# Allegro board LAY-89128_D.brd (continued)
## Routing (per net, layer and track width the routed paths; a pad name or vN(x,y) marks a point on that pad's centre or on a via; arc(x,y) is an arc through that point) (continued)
P3V3_SDA: length 29.5
  TOP w0.203: C79.1 155.04,44.04 U25.1
  TOP w0.305: v2(163.62,37.16) 164.03,37.57 C155.1 ; v2(150.39,38.02) 150.01,37.64 U27.5 ; C160.1 162.6,42.19 v2(162.9,42.49)
  TOP w0.381: R202.1 163.67,46.29 v2(163.74,46.36) 164.34,46.96 C94.1
  TOP w0.457: v2(171.42,43.71) 171.42,43.48 170.97,43.03 170.57,43.03 C82.1
  TOP w0.508: v2(166.24,35.5) 166.27,35.54 R197.1 ; v2(165.03,47.95) 165.03,47.91 165.47,47.48 165.47,46.93 C83.1 ; R186.1 157.56,45.03 v2(156.79,45.8)
  BOTTOM w0.254: U26.7 169.35,46.04 169.66,46.35 169.87,46.35 169.9,46.38 169.9,46.38 v3(170.26,46.74) ; U26.11 171.2,43.93 v2(171.42,43.71) ; U28.1 164.12,37.45 163.83,37.16 v2(163.62,37.16) ; U19.1 160.57,38.09 v3(160.46,38.2)
  BOTTOM w0.305: U29.1 162.6,42.11 162.9,42.41 v2(162.9,42.49) ; v2(165.03,47.95) 165.03,47.92 165.43,47.53 165.43,46.95 166.35,46.02 U26.1
  BOTTOM w0.381: R199.1 v2(173.41,35.93) ; v3(156.03,47.88) 156.78,47.13 156.78,45.81 v2(156.79,45.8) ; v2(163.74,46.36) 163.8,46.3 U20.1
  BOTTOM w0.508: C80.1 R190.2 ; C80.1 R187.1 ; C80.1 149.5,37.77 149.76,38.02 v2(150.39,38.02)
  vias: v3(159.71,42.07)
P5V0_SDA_USB_CONN_VBUS: length 6.7
  TOP w0.381: J57.1 180.84,40.15 179.66,38.97 L4.1 179.46,38.97 178.58,39.85 177.35,39.85 176.97,40.23 U17.6
P5V_SDA: length 2.7
  TOP w0.508: R198.1 170.05,39.12 v2(170.73,39.79)
  BOTTOM w0.305: v2(169.26,46.96) 169.26,46.62 168.85,46.22 U26.6
  vias: v2(177.1,36.09) v2(177.1,34.82) v2(178.37,36.09) v2(178.37,34.82) v3(165.65,45.69)
VBAT: length 2.2
  TOP w0.508: v2(97.43,37.38) 97.99,37.95 P1.49
  vias: v2(96.54,36.24) v2(96.54,35.1) v2(97.56,36.24) v2(97.56,35.1)
VBATPWR: length 2
  TOP w0.508: P1.46 v2(101.8,41.42)
  vias: v2(100.86,41.7) v2(100.86,40.81)
VBUS_DC: length 5.1
  TOP w0.305: J7.B4 158.24,53.29 157.99,53.04 J7.A9 157.99,51.53 157.68,51.23 ; J7.B9 160.74,53.29 160.99,53.04 J7.A4 160.99,51.81 161.16,51.64
  vias: v2(158.22,49.71)
VBUS_PA: length 6.1
  TOP w0.305: D4.C 176.58,50.98 176.99,51.39 J6.A4 176.99,53.04 176.74,53.29 J6.B9 ; v2(173.99,51.51) J6.A9 173.99,53.04 174.24,53.29 J6.B4
VDDIO: length 2.1
  TOP w0.508: v2(104.34,37.28) v2(104.34,38.17) P1.44
  vias: v2(106.95,40.56) v2(107.97,40.56) v2(109.04,40.64) v2(110.89,41.45)
VDDIO_BRD: length 54.5
  TOP w0.305: Q1.1 123.73,43.43 124.1,43.05 v2(129.23,43.05)
  TOP w0.508: v2(120.06,9.35) 119.63,9.78 R71.2 ; v2(120.06,9.35) 120.39,9.35 120.9,9.86 R56.2 ; v2(120.06,9.35) 120.75,8.67 122.72,8.67 123.44,9.38 R67.2 124.14,10.08 124.38,10.33 v2(124.38,16.76) 124.38,17.01 J28.1 ; J12.2 95.13,8.09 96.35,9.31 R7.2 ; R91.1 R90.1 111.45,30.98 v2(111.66,31.19)
  BOTTOM w0.305: SH7.2 131.01,41.27 v2(129.23,43.05)
  BOTTOM w0.381: R69.1 175.54,15.2 R62.1 175.54,13.41 175.08,12.95 v2(174.07,12.95)
  BOTTOM w0.457: SH6.1 118.44,41.25 v2(118.41,41.27)
  BOTTOM w0.508: TP6.1 123.11,15.49 v2(124.38,16.76) ; v2(120.06,9.35) 119.71,9.7 R68.1 ; SH5.1 114.97,39.3 v2(115.43,39.75)
  vias: v2(171.1,11.47) v2(171.11,10.31) v2(171.22,12.49) v2(172.37,11.47) v2(172.38,10.31) v2(172.49,12.49)
VDDPA: length 2.5
  TOP w0.508: 94.18,39.4 v2(94.18,38.09)
  BOTTOM w0.508: R26.2 v2(94.18,38.09)
ANT_1: length 554.1
  TOP w0.4: J29.2 51.81,28.73 51.52,29.01 47.31,29.01 arc(47.11,28.97) 46.93,28.85 46.73,28.65 arc(46.71,28.62) 46.7,28.58 46.7,7.9 arc(46.59,7.62) 46.3,7.5 2.1,7.5 arc(1.82,7.62) 1.7,7.9 1.7,52.1 arc(1.82,52.38) 2.1,52.5 46.3,52.5 arc(46.58,52.38) 46.7,52.1 46.7,29.75 46.1,29.15 46.1,8.5 arc(45.98,8.22) 45.7,8.1 2.7,8.1 arc(2.42,8.22) 2.3,8.5 2.3,51.5 arc(2.42,51.78) 2.7,51.9 45.7,51.9 arc(45.98,51.78) 46.1,51.5 46.1,30.15 45.5,29.55 45.5,9.1 arc(45.38,8.82) 45.1,8.7 3.3,8.7 arc(3.02,8.82) 2.9,9.1 2.9,50.9 arc(3.02,51.18) 3.3,51.3 45.1,51.3 arc(45.38,51.18) 45.5,50.9 v2(45.5,31)
  TOP w0.505: R80.2 R73.2 59.41,28.72 59.4,28.73 J30.2 J29.2 ; J29.3 J30.3 59.41,31.27 59.42,31.27 R79.2 60.23,31.28 R74.2
  BOTTOM w0.4: v2(45.5,31) 51.74,31 arc(51.93,31.08) J29.3
C_TX1: length 11.5
  TOP w0.505: C105.2 C97.2 ; C97.2 R75.2 ; C97.2 65.64,33.17 C95.2 63.75,33.19 C98.2 62.18,33.16 R74.1 62.16,31.28 R79.1
C_TX2: length 11.5
  TOP w0.505: C103.2 R81.2 ; C103.2 65.64,26.82 C100.1 C96.1 R80.1 R73.1 ; C103.2 C101.2
DC5V: length 18.1
  TOP w0.508: 151.59,23.88 152.88,22.58 154.89,22.58 155.49,21.98 155.49,16.09 v2(152.84,13.45)
  BOTTOM w0.508: C134.1 129.92,33.87 129.55,33.5 J43.4 ; SJ10.1 152.84,12.15 v2(152.84,13.45)
EXT_MODE_SWITCH_SP: length 40.2
  BOTTOM w0.114: J27.6 185.39,27.21 185.39,31.55 184.41,32.53 179.09,32.53 177.83,33.79 177.75,33.79 177.74,33.79 158.44,33.79 155.53,36.7 154.5,36.7 153.87,36.07 R144.2
EXT_MODE_SWITCH_SP_DONE: length 41.4
  BOTTOM w0.114: R122.1 155.27,36.07 157.8,33.54 177.73,33.54 178.99,32.29 184.31,32.29 185.15,31.45 185.15,28.06 184.05,26.97 183.7,26.97 183.1,26.37 183.1,24.43 J27.8
EXTAL32: length 2.8
  TOP w0.114: Y1.1 119.3,38.5 120.36,37.43 120.36,36.8 U22.L5
GREEN_LED: length 25.6
  TOP w0.114: v1(158.34,12.12) 157.28,12.12 155.92,13.47 155.92,23.73 156.15,23.96 R15.2 156.51,24.85 156.43,24.94 154.74,24.94 J43.19
  BOTTOM w0.114: v1(158.34,12.12) 158.76,12.12 158.79,12.15 SJ8.1
J_VBATPWR:
  vias: v2(106.27,44.91) v2(106.27,43.89) v2(106.27,42.88)
J_VUP:
  vias: v2(98.48,46.18) v2(98.48,45.3) v2(99.45,46.15) v2(99.45,45.26)
JTAG_TDO: length 2.8
  TOP w0.114: J28.6 R56.1
JTAG_TMS_SWDIO: length 27.9
  TOP w0.114: P1.25 101.8,15.67 102.79,14.68 v2(104.74,14.68) ; R67.1 v1(123.44,12.07) J28.2
  BOTTOM w0.114: v1(123.44,12.07) 121.92,13.59 107.26,13.59 106.17,14.68 v2(104.74,14.68)
K82_JTAG_RST: length 2.5
  TOP w0.114: J35.10 119.02,45 SH2.2
K82_MODE_SWITCH_SP: length 71.6
  TOP w0.114: v2(116.15,29.34) 116.46,29.65 116.97,29.65 117.23,29.91 117.23,30.43 U22.B9
  BOTTOM w0.114: J27.5 179.62,25.94 179.28,26.28 172.8,26.28 172.52,26.57 172.52,27.85 171.69,28.67 138.73,28.67 136.6,26.54 130.65,26.54 129.3,27.89 125.46,27.89 125,28.35 117.58,28.35 116.59,29.34 v2(116.15,29.34)
K82_MODE_SWITCH_SP_DONE: length 73.8
  TOP w0.114: U22.D8 117.88,31.73 117.88,29.67 v2(116.66,28.45)
  BOTTOM w0.114: J27.7 178.97,26.02 172.72,26.02 172.27,26.47 172.27,27.75 171.59,28.43 138.99,28.43 136.85,26.29 130.38,26.29 129.02,27.65 125.36,27.65 124.9,28.11 117,28.11 v2(116.66,28.45)
K82_NFC_IRQ: length 94.1
  TOP w0.114: U22.F8 117.88,33.68 115.7,33.68 v1(115.54,33.53)
  BOTTOM w0.114: J27.19 177.71,8.16 169.96,15.92 161.66,15.92 160.29,14.55 155.92,14.55 155.58,14.89 137.77,14.89 137.43,14.55 114.31,14.55 113.87,14.99 113.87,27.41 114.11,27.66 114.11,32.1 v1(115.54,33.53)
K82_PTA20: length 74.6
  TOP w0.114: U22.H5 v1(119.83,34.98)
  BOTTOM w0.114: J27.1 138.96,31.02 138.52,30.58 138.52,29.23 136.35,27.05 131.51,27.05 130.19,28.37 125.66,28.37 125.2,28.83 119.33,28.83 117.3,30.86 117.3,33.61 118.05,34.37 119.23,34.37 v1(119.83,34.98)
K82_PTA21: length 76.6
  TOP w0.114: U22.J5 v1(119.83,35.63)
  BOTTOM w0.114: J27.3 179.3,30.76 139.04,30.76 138.76,30.48 138.76,29.09 136.47,26.8 131.02,26.8 129.68,28.13 125.56,28.13 125.1,28.59 119.19,28.59 117.04,30.73 117.04,33.67 117.97,34.59 118.8,34.59 v1(119.83,35.63)
K82_SPI1_CLK: length 81.5
  TOP w0.114: v1(115.67,31.09) 115.7,31.06 116.57,31.06 U22.C10
  BOTTOM w0.114: J27.13 180.54,16.83 180.54,19.69 179.91,20.32 179.91,24.26 179.49,24.67 171.98,24.67 171.97,24.66 171.93,24.66 171.53,24.26 163.9,24.26 160.46,27.71 139.67,27.71 137.49,25.53 126.8,25.53 124.7,27.62 116.53,27.62 115.4,28.75 115.4,30.82 v1(115.67,31.09)
K82_SPI1_CS0: length 85.1
  TOP w0.114: U22.D10 116.59,31.73 115.32,31.73 v1(115.24,31.65)
  BOTTOM w0.114: J27.15 179.91,14.92 179.91,19.63 179.54,20 179.54,24.28 179.39,24.43 172.08,24.43 171.66,24.02 163.46,24.02 160.01,27.46 140.06,27.46 137.87,25.27 126.69,25.27 124.59,27.38 116.43,27.38 115.14,28.67 115.14,31.16 115.24,31.26 v1(115.24,31.65)
K82_SPI1_MISO: length 81.5
  TOP w0.114: v1(115.59,32.32) 115.65,32.38 117.24,32.38 U22.E9
  BOTTOM w0.114: J27.11 181.58,19.35 180.16,20.77 180.16,24.43 178.81,25.78 172.62,25.78 172.03,26.37 172.03,27.65 171.49,28.19 139.13,28.19 136.98,26.04 129.62,26.04 128.24,27.41 125.26,27.41 124.8,27.86 116.63,27.86 115.72,28.77 115.72,30.16 116.06,30.5 116.06,31.85 v1(115.59,32.32)
K82_SPI1_MOSI: length 86.9
  TOP w0.114: v1(114.63,29.34) 115.72,30.42 116.58,30.42 U22.B10
  BOTTOM w0.114: J27.17 179.4,12.89 179.4,15.98 178.74,16.64 173.05,16.64 170.59,19.09 158.11,19.09 154.81,15.8 128.29,15.8 125.42,18.67 121.61,18.67 121.23,19.05 117.08,19.05 114.36,21.77 114.36,27.56 114.63,27.83 v1(114.63,29.34)
LEDGR: length 2.1
  TOP w0.114: D3.A v1(178.79,23.9)
  BOTTOM w0.114: R178.2 v1(178.79,23.9)
LEDRR: length 2.1
  TOP w0.114: D2.A v1(178.79,22.69)
  BOTTOM w0.114: v1(178.79,22.69) 178.38,22.69 178.36,22.71 R177.2
LP3856_ADJ_R: length 9.8
  TOP w0.508: J3.1 137.67,20.02 C20.2 140.05,20.02 R28.2 140.18,20.09 R5.1 140.88,19.28 141.35,19.75 141.46,19.86 142.57,19.86 142.9,19.52 U5.5
LVLRST_EN: length 1.3
  TOP w0.114: R188.1 155.02,47.38 155.04,47.35 U25.5
MCU_VBAT: length 3.7
  TOP w0.254: U22.K6 v1(119.18,35.62)
  BOTTOM w0.457: SH6.2 118.44,36.96 119.02,36.37 C52.1 119.18,36.34 v1(119.18,35.62)
MCU_VDD: length 15.8
  TOP w0.203: U22.L10 116.91,37.12 116.79,37.24 116.51,37.24 v2(116.15,37.59)
  TOP w0.254: U22.E7 v1(118.53,32.38) ; U22.E6 v1(119.18,32.38)
  TOP w0.508: C41.1 115.39,50.39 116.15,49.63 116.19,49.63 116.32,49.5 J35.1 117.18,50.37 116.67,50.88 R36.1 ; R38.1 122.12,46.08 v2(122.81,46.08) ; R183.1 v2(113.52,27.69)
  BOTTOM w0.305: C55.1 117.87,32.38 v1(118.53,32.38) 118.53,31.8 C56.1 119.18,31.83 v1(119.18,32.38) 119.27,32.28 C54.1
  BOTTOM w0.508: U23.5 113.52,27.69 v2(113.52,27.69) ; R180.1 116.33,37.77 v2(116.15,37.59) ; v2(121.74,29.46) 122.25,29.97 SH4.1
MCU_VDDA: length 4.9
  TOP w0.254: U22.G5 v1(120.48,34.33) ; U22.F5 v1(120.48,33.68)
  BOTTOM w0.305: v1(120.48,34.33) v1(120.48,33.68)
  BOTTOM w0.508: v1(120.48,34.33) 120.52,34.29 C51.1 ; SH4.2 121.96,32.29 121.76,32.49 121.52,32.85 121.39,33.15 121.23,33.31 C50.1 120.96,33.68 v1(120.48,33.68)
NFC_AUX1: length 11.8
  TOP w0.114: J10.3 87.4,9.44 92.91,14.96 P1.18
NFC_AUX2: length 14.8
  TOP w0.114: J10.2 88.95,7.14 88.95,9.75 94.18,14.99 94.18,17.6
NFC_CLK: length 2.4
  TOP w0.114: TP33.1 97.99,16.37 P1.22
NFC_CLK_AUX: length 87.6
  TOP w0.114: 89.1,39.4 87.91,39.4 86.11,41.19 v2(84.98,41.19) 84.5,41.68 TP50.1
  BOTTOM w0.114: v2(84.98,41.19) 84.98,42.19 84.05,43.13 84.05,48.49 81.71,50.83 81.71,56.41 83.67,58.37 139.86,58.37 J15.5
NFC_DWL_REQ: length 52
  TOP w0.114: P1.27 104.34,16.54 104.62,16.26 v2(104.62,15.82)
  BOTTOM w0.114: v2(104.62,15.82) 106.89,15.82 110.14,19.07 110.14,24.1 107.91,26.32 107.91,39.33 108.75,40.18 109.2,40.18 109.55,40.53 109.55,41.53 111.71,43.69 112.89,43.69 114.67,45.46 114.67,52.21 113.05,53.83 111.37,53.83 J14.1
NFC_GPIO0: length 55.2
  TOP w0.114: TP19.1 v2(108,17.6) P1.28
  BOTTOM w0.114: v2(108,17.6) 108,25.55 107.39,26.16 107.39,42.29 109.55,44.45 112.3,44.45 114.18,46.33 114.18,52.01 112.94,53.25 105.35,53.25 J13.9
NFC_GPIO1: length 47.1
  TOP w0.114: P1.31 v2(109.7,22.79) 110.64,22.79 110.65,22.78 TP18.1
  BOTTOM w0.114: J13.10 107.58,53.56 112.97,53.56 114.42,52.11 114.42,46.19 112.3,44.07 109.8,44.07 108.45,42.72 108.45,40.3 107.67,39.52 107.67,26.22 109.7,24.19 v2(109.7,22.79)
NFC_GPIO3: length 5
  TOP w0.114: P1.30 110.43,21.52 112.03,19.91 R8.1
NFC_GPIO4: length 41
  TOP w0.114: P1.32 v2(110.69,24.06) TP16.1
  BOTTOM w0.114: J14.2 114.91,52.84 114.91,45.36 112.91,43.37 111.89,43.37 109.93,41.4 109.93,40.55 109.31,39.94 108.85,39.94 108.15,39.23 108.15,26.6 v2(110.69,24.06)
NFC_GPIO5: length 67.9
  TOP w0.114: TP17.1 P1.33 107.08,25.33 v2(107.01,25.4)
  BOTTOM w0.114: v2(107.01,25.4) 107.01,30.73 106.27,31.47 106.27,41.68 109.68,45.08 112.6,45.08 113.94,46.43 113.94,51.91 112.93,52.92 103.67,52.92 102.59,54 102.59,55.8 101.98,56.41 87.55,56.41 J13.2
NFC_GPIO6: length 42.7
  TOP w0.114: v2(90.37,19.48) P1.16 TP25.1
  BOTTOM w0.114: J13.6 96.14,49.84 91.26,44.96 91.26,21.81 91.15,21.7 91.15,21.33 91.26,21.22 91.26,20.53 91.15,20.42 91.15,20.25 v2(90.37,19.48)
NFC_GPIO7: length 50
  TOP w0.114: v2(91.59,21.52) P1.13 85.02,21.52 84.07,20.57 84.07,19 TP26.1
  BOTTOM w0.114: J13.7 96.52,52.68 96.52,49.71 91.59,44.78 v2(91.59,21.52)
NFC_GPIO8: length 48.1
  TOP w0.114: TP27.1 86.46,19.28 P1.14 87.68,20.25 88.18,20.75 v2(90.37,20.75)
  BOTTOM w0.114: J13.5 93.6,48.01 90.88,45.29 90.88,21.26 v2(90.37,20.75)
NFC_GPIO9: length 47.1
  TOP w0.114: TP28.1 89.1,15.47 89.1,19.28 90.06,20.24 v2(91.59,20.24)
  BOTTOM w0.114: J13.8 100.21,54.84 96.88,51.51 96.88,49.31 92.28,44.7 92.28,20.93 v2(91.59,20.24)
NFC_HOST_SEL0: length 6.5
  TOP w0.114: v2(95.45,16.13) 95.45,17.6 ; v1(94.94,12.22) 94.94,11.51 R7.1
  BOTTOM w0.114: v1(94.94,12.22) 94.94,15.62 v2(95.45,16.13)
NFC_HOST_SEL1: length 2.8
  TOP w0.114: R89.2 96.72,17.6
NFC_I2C_IRQ: length 173
  TOP w0.114: TP15.1 82.21,37.97 83.11,37.07 83.11,36.17 v1(84.49,34.79) 84.78,34.5 84.98,34.5 85.26,34.22 P1.3 ; v1(174.32,28.32) 175.17,28.32 176.19,27.3 184.56,27.3 185.27,26.6 185.27,7.62 184.25,6.6 174.32,6.6 v1(173.81,7.11)
  BOTTOM w0.114: R152.2 174.95,27.69 v1(174.32,28.32) ; v1(84.49,34.79) 84.91,34.79 89.61,30.08 89.61,19.62 90.19,19.04 90.77,19.04 91.46,19.73 101.79,19.73 102.95,18.57 102.95,13.41 106.07,10.29 125.42,10.29 126.95,11.81 136.47,11.81 137.24,11.05 137.24,3.56 139.27,1.52 162.51,1.52 169.11,8.13 172.8,8.13 v1(173.81,7.11)
NFC_I2C_SCL: length 46.9
  TOP w0.114: R90.2 110.79,33.07 v2(109.49,34.37) 109.49,34.3 109.4,34.22 P1.40 ; v1(125.09,48.72) 125.09,48.08 126.95,46.23 128.17,46.23 130.33,44.07 130.33,39.6 131.11,38.81 R127.2
  BOTTOM w0.114: v2(109.49,34.37) 109.49,38.89 115.54,44.95 115.54,50.12 116.07,50.65 123.16,50.65 v1(125.09,48.72)
NFC_I2C_SDA: length 61
  TOP w0.114: R91.2 109.93,32.56 v2(109.6,32.89) 109.55,32.95 P1.39 ; R137.2 129.59,38.91 130.09,39.41 130.09,43.97 128.08,45.97 126.8,45.97 v1(124.26,48.51) ; R8.2 v1(111.4,21.17)
  BOTTOM w0.114: v1(111.4,21.17) 112.64,22.41 112.64,30.94 110.69,32.89 v2(109.6,32.89) 109.93,33.22 109.93,38.99 115.78,44.85 115.78,50.02 116.17,50.41 122.98,50.41 124.26,49.14 v1(124.26,48.51)
NFC_INT_AUX: length 90.4
  TOP w0.114: 91.64,39.4 91.64,38.2 91.11,37.67 87.86,37.67 86.24,39.29 v2(85.24,39.29) 83.86,39.29 TP43.1
  BOTTOM w0.114: v2(85.24,39.29) 85.24,40.66 85.52,40.94 85.52,42.41 84.45,43.48 84.45,48.84 82.14,51.16 82.14,56.29 83.87,58.01 137.67,58.01 J15.4
NFC_IO_AUX: length 83.4
  TOP w0.114: TP39.1 83.64,40.03 83.79,40.18 v2(85.7,40.18) 86.26,40.18 88.17,38.27 90.18,38.27 90.37,38.47 P1.55
  BOTTOM w0.114: J15.3 135.61,57.53 86.13,57.53 84.78,56.19 84.78,53.72 84.4,53.34 83.13,53.34 82.83,53.04 82.83,51.23 85.17,48.89 85.17,43.81 85.93,43.05 85.93,40.85 85.7,40.62 v2(85.7,40.18)
NFC_IRQ: length 130.4
  TOP w0.114: P1.26 103.07,16.08 103.88,15.27 105.43,15.27 105.83,14.87 105.83,13.93 105.49,13.59 105.1,13.59 104.47,12.95 96.32,12.95 96.04,13.23 92.94,13.23 90.41,10.71 90.41,4.38 93.41,1.38 104.99,1.38 106.81,3.21 SJ4.1 v1(109.97,3.21)
  BOTTOM w0.114: v1(109.97,3.21) 109.97,2.12 110.44,1.65 117.47,1.65 117.85,1.27 162.76,1.27 169.35,7.85 172.49,7.85 174.12,6.22 181.77,6.22 182.99,7.44 183.4,7.44 J27.20
NFC_JTAG_RST: length 6.5
  TOP w0.114: D12.1 D12.2 R60.2 115.57,8.31 TP24.1
NFC_MODE_SWITCH: length 114.2
  TOP w0.114: R16.2 v1(158.22,25.5) ; P1.29 110.74,20.25 111.5,19.49 111.5,18.01 111.97,17.54 v2(111.97,16.06) 111.05,15.14 106.78,15.14 106.09,14.45 106.09,13.68 104.21,11.81 101.68,11.81 100.91,12.57 96.19,12.57 95.84,12.92 93.14,12.92 90.8,10.59 90.8,4.57 93.68,1.7 101.7,1.7 103.18,3.18 SJ3.1 ; v1(113.18,15.32) 113.31,15.44 113.31,23.3 113.97,23.96 R141.1 114.73,24.75 114.84,24.86 v1(114.88,24.86)
  BOTTOM w0.114: v1(113.18,15.32) 112.71,15.32 v2(111.97,16.06) ; v1(158.22,25.5) 156.49,27.22 140.45,27.22 138.25,25.02 126.61,25.02 124.52,27.11 116.39,27.11 114.88,25.6 v1(114.88,24.86)
NFC_RXN: length 17.9
  TOP w0.505: R75.1 R76.2 72.08,35.71 arc(72.89,35.55) J32.6 J31.6 arc(81.04,33.53) 83.77,32.99 84.73,32.99 arc(85,32.96) 85.28,32.95 P1.4
NFC_RXP: length 17.5
  TOP w0.505: P1.10 79.72,25.33 arc(79.19,25.22) J31.2 J32.2 arc(72.89,24.45) 72.08,24.28 R77.1 R81.1
NFC_SPI_CLK: length 119.4
  TOP w0.114: J27.14 183.02,14.68 183.02,7.48 182.38,6.85 175.86,6.85 v1(175.21,7.49) ; P1.35 v1(106.49,27.87)
  BOTTOM w0.114: v1(106.49,27.87) 103.94,25.32 103.94,13.43 106.06,11.32 124.17,11.32 125.93,13.08 137.11,13.08 138.63,11.56 138.63,4.06 140.03,2.67 162.38,2.67 168.99,9.27 173.43,9.27 v1(175.21,7.49)
NFC_SPI_MISO: length 119.8
  TOP w0.114: v1(177.24,7.49) 177.65,7.09 182.28,7.09 182.78,7.58 182.78,16.98 J27.12 ; P1.34 v1(106.49,26.6)
  BOTTOM w0.114: v1(177.24,7.49) 176.83,7.49 174.67,9.65 168.86,9.65 162.25,3.05 140.41,3.05 139.14,4.32 139.14,11.56 137.24,13.46 125.68,13.46 123.86,11.65 106.07,11.65 104.18,13.53 104.18,24.29 v1(106.49,26.6)
NFC_SPI_MOSI: length 117.3
  TOP w0.114: P1.37 v1(106.49,30.41)
  BOTTOM w0.114: J27.18 183.08,9.66 183.08,7.88 181.94,6.73 174.78,6.73 173,8.51 169.11,8.51 162.51,1.9 139.65,1.9 137.74,3.81 137.74,11.18 136.73,12.19 126.57,12.19 125.04,10.67 106.03,10.67 103.46,13.23 103.46,27.38 v1(106.49,30.41)
NFC_SPI_NSS: length 117.7
  TOP w0.114: P1.36 v1(106.49,29.14)
  BOTTOM w0.114: v1(106.49,29.14) 103.7,26.35 103.7,13.33 105.99,11.05 124.66,11.05 126.19,12.57 136.98,12.57 138.25,11.3 138.25,3.94 139.9,2.29 162.51,2.29 169.11,8.89 172.96,8.89 174.77,7.08 181.95,7.08 182.7,7.84 182.7,11.82 J27.16
NFC_TX1: length 21.1
  TOP w0.505: C105.1 C97.1 arc(69.97,32.7) 70.8,32.54 C93.2 ; C93.2 R76.1 ; C93.2 72.21,32.54 72.22,32.55 J32.5 J31.5 arc(80.7,31.22) 83.03,30.76 C102.1 85.61,30.76 arc(86.07,30.67) P1.6
NFC_TX2: length 20.6
  TOP w0.505: C92.1 70.8,27.46 arc(69.97,27.29) C103.1 C101.1 ; C92.1 R77.2 ; C92.1 72.21,27.46 72.22,27.47 J32.3 J31.3 arc(79.19,27.76) 79.72,27.87 C104.1 P1.8
NFC_VEN: length 126.4
  TOP w0.114: v1(156.72,13.4) 156.72,13.82 156.51,14.03 R15.3 157.35,22.28 157.35,25 156.72,25.63 155.24,25.63 154,26.87 154,30.21 154.56,30.76 173.71,30.76 174.07,30.4 174.07,29.16 174.47,28.75 175.4,28.75 175.83,28.32 178.13,28.32 178.61,28.8 v1(178.61,29.92) ; P1.43 108.93,39.4 v2(108.93,39.4)
  BOTTOM w0.114: v2(108.93,39.4) 108.39,38.86 108.39,26.98 111.13,24.24 111.13,21.49 110.98,21.34 110.98,18.63 113.59,16.02 113.59,14.62 114.2,14.01 138.76,14.01 139.35,14.61 155.52,14.61 v1(156.72,13.4) 156.72,12.15 SJ9.1 ; v1(178.61,29.92) 178.32,29.63 178.32,29.53 178.17,29.38 178.17,27.85 177.72,27.41 R142.1
NMI_B: length 2.3
  TOP w0.114: U22.J8 117.88,35.62 v1(117.88,36.28)
  BOTTOM w0.114: R180.2 117.39,36.28 v1(117.88,36.28)
NRESET: length 3.1
  TOP w0.114: D12.3 117.48,11.98 118.36,12.87 J28.10
PTA0: length 38.1
  TOP w0.114: J35.4 119.9,49.68 120.67,49.68 R37.1 122.73,51.74 137.55,51.74 139.9,49.39 J60.1 ; U22.L7 118.2,37.26 118.2,39.83 119.98,41.61 v1(119.98,42.02)
  BOTTOM w0.114: v1(119.98,42.02) 119.3,42.7 119.3,47.38 J35.4
PTA1: length 25.9
  TOP w0.114: v1(123.37,45.29) 123.37,46.76 123.21,46.91 123.21,47.01 122.93,47.29 R47.2 ; U22.H8 v1(117.88,34.98)
  BOTTOM w0.114: v1(123.37,45.29) 123.37,44.88 123.36,44.87 123.36,44.67 122.94,44.25 122.94,41.94 122.32,41.32 119.79,41.32 119.07,42.04 115.41,42.04 113.6,40.23 113.6,36.79 114.32,36.07 116.79,36.07 v1(117.88,34.98)
PTA2: length 21.8
  TOP w0.114: R39.2 122.4,48.72 122.4,48.42 124.2,46.62 124.2,45.14 123.77,44.71 v1(123.77,44.3) ; U22.J7 v1(118.53,34.98)
  BOTTOM w0.114: v1(123.77,44.3) 123.36,44.3 123.18,44.12 123.18,41.84 122.42,41.08 119.26,41.08 118.62,41.71 117.92,41.71 117.8,41.6 117.8,37.04 118.31,36.54 118.31,35.96 118.53,35.74 v1(118.53,34.98)
PTA3: length 51.6
  TOP w0.114: R36.2 118.45,50.75 J35.2 120.99,52.04 139.45,52.04 J59.1 ; U22.H9 117.23,34.98 v1(116.58,34.98)
  BOTTOM w0.114: v1(116.58,34.98) 116.25,35.31 114.74,35.31 113.36,36.69 113.36,40.33 116.03,43 116.03,49.92 116.27,50.17 117.78,50.17 J35.2
PTA18: length 7.4
  TOP w0.114: C152.2 Y2.3 111.71,35.8 111.82,35.69 113.98,35.69 113.98,35.69 114.35,35.69 R181.2 115.06,36.4 116.05,36.4 U22.L11
PTA19: length 7.5
  TOP w0.114: C153.2 113.28,33.29 113.31,33.32 Y2.1 113.31,35.31 113.45,35.45 114.01,35.45 114.12,35.33 114.12,34.92 114.22,34.83 R181.1 114.91,34.83 115.04,34.95 115.04,36.02 115.17,36.15 116.05,36.15 U22.K11
PTC7: length 4.7
  TOP w0.114: SJ12.1 118.53,27.11 118.53,27.11 118.53,27.6 119.19,28.26 119.19,30.41 U22.B7
PTC8: length 4.2
  TOP w0.114: SJ13.1 117.39,26.48 117.39,27.25 118.86,28.71 U22.A7
PU-R_RST_B: length 3.8
  TOP w0.114: C91.1 v1(116.71,9.7) 116.21,9.7 R60.1
  BOTTOM w0.114: R68.2 v1(116.71,9.7)
PWR_ON: length 2.1
  TOP w0.114: D1.A v1(178.79,25.22)
  BOTTOM w0.114: v1(178.79,25.22) R20.2
R_5V0_ADJ: length 3
  TOP w0.508: J3.2 R6.1
RST_TGTMCU_B: length 132.8
  TOP w0.114: R183.2 113.52,30.32 113.52,30.32 v1(113.52,30.73) 113.91,31.12 113.91,33.28 115.93,35.3 U22.J11 ; v1(129.23,44.2) 128.8,43.76 123.6,43.76 123.16,44.2 123.16,44.85 123.02,45 SH2.1 122.28,45 121.81,44.53 121.8,44.53 121.54,44.27 119.46,44.27 118.95,43.76 118.73,43.76 118.73,43.76 115.84,43.76 v1(115.52,43.43) ; v1(144.63,53.19) 145.44,52.37 151.55,52.37 154.29,49.63 156.17,49.63 157.16,48.64 161.72,48.64 162.53,49.45 164.08,49.45 164.64,50.01 171.65,50.01 173.18,48.49 175.49,48.49 175.84,48.13 175.84,38.15 174.62,36.93 D8.C ; U25.7 153.5,45.87 152.97,45.34 v1(151.84,45.34)
  BOTTOM w0.114: v1(151.84,45.34) 151.33,45.85 149.43,45.85 147.9,47.37 147.9,52.38 147.39,52.9 144.92,52.9 v1(144.63,53.19) R195.2 143.76,51.99 141.68,49.91 138.89,49.91 138.25,49.28 138.25,40.95 139.17,40.04 J56.3 136.22,42.04 135.24,42.04 134.57,42.71 R185.2 133.94,43.03 133.84,42.93 133.84,42.44 133.44,42.04 131.81,42.04 129.65,44.2 v1(129.23,44.2) ; U23.4 v1(113.52,30.73) 113.52,32.06 114.24,32.77 114.24,35.19 112.98,36.45 112.98,40.89 v1(115.52,43.43)
SDA_EXTAL: length 5.5
  BOTTOM w0.114: U26.17 169.85,40.03 170.81,39.08 X1.3 170.81,37.37 171.78,36.4 C88.1
SDA_JTAG_TCLK: length 32.4
  TOP w0.114: v1(157.6,38.2) 158.11,37.69 158.11,35.9 160.2,33.81 169.2,33.81 171.78,36.39 171.78,40.4 173.56,42.18 v2(173.56,42.93)
  BOTTOM w0.114: v2(173.56,42.93) 173.25,43.24 171.25,43.24 171.05,43.43 U26.12 ; v1(157.6,38.2) 156.69,39.12 156.2,39.12 J62.4
SDA_JTAG_TDI: length 30.3
  TOP w0.114: v1(158.95,36.53) 158.95,35.92 160.43,34.44 167.4,34.44 171.19,38.24 171.19,41.15 v2(172.5,42.46)
  BOTTOM w0.114: v2(172.5,42.46) 172.03,42.93 U26.13 ; J62.8 154.55,38.23 156.38,38.23 158.08,36.53 v1(158.95,36.53)
SDA_JTAG_TDO: length 33.2
  TOP w0.114: v2(173.81,41.71) 172.11,40 172.11,36.38 169.29,33.55 159.92,33.55 157.7,35.78 v1(157.7,37.49)
  BOTTOM w0.114: U26.14 171.2,42.43 171.62,42.02 173.5,42.02 v2(173.81,41.71) ; J62.6 155.58,38.47 156.72,38.47 v1(157.7,37.49)
SDA_JTAG_TMS: length 30.2
  TOP w0.114: v2(172.29,41.53) 171.47,40.72 171.47,38.18 167.41,34.11 160.32,34.11 158.54,35.9 158.54,36.85 v1(159.35,37.67) ; R207.2 157.89,40.49 J62.2
  BOTTOM w0.114: v1(159.35,37.67) 159.06,37.96 158.62,37.96 J62.2 ; U26.15 171.3,41.93 171.7,41.53 v2(172.29,41.53)
SDA_LED: length 21
  TOP w0.114: v2(164.51,43.62) 165.18,42.95 165.18,42.26 166.37,41.07 170.18,41.07 TP74.1 172.94,43.83 173.56,43.83 174.25,43.14 174.25,41.15 172.83,39.74 172.83,37.51 173.41,36.93 D9.C
  BOTTOM w0.114: U26.29 165.13,43.43 164.95,43.62 v2(164.51,43.62)
SDA_LED_R: length 2.4
  TOP w0.114: D9.A v1(173.41,39.49)
  BOTTOM w0.114: v1(173.41,39.49) R199.2
SDA_RST: length 27.2
  TOP w0.114: v2(168.5,39.84) 168.85,39.49 R198.2 TP72.1 168.85,36.24 167.3,34.68 160.77,34.68 v1(159.86,35.59)
  BOTTOM w0.114: v1(159.86,35.59) 158.67,35.59 156.29,37.97 154,37.97 152.15,39.82 151.68,39.82 J62.10 R83.1 ; v2(168.5,39.84) 168.85,40.2 U26.19
SDA_RST_LED: length 2.5
  TOP w0.114: D8.A 174.7,38.53 v1(174.7,39.5)
  BOTTOM w0.114: R191.2 v1(174.7,39.5)
SDA_RST_TGTMCU_B: length 30.8
  TOP w0.114: v2(167.4,39.58) 164.94,42.04 164.94,42.48 164.54,42.87 163.49,42.87 161.71,44.66 161.71,46.52 159.84,48.39 157.05,48.39 156.04,49.39 154.01,49.39 153.5,49.9 148.65,49.9 147.27,48.51 147.27,47 J58.2
  BOTTOM w0.114: v2(167.4,39.58) 167.71,39.89 167.71,40.12 167.85,40.26 U26.21
SDA_RST_TGTMCU_J_B: length 45.1
  TOP w0.114: R186.2 156.54,44.58 v1(156.51,44.62) 156.51,45.36 156.39,45.47 U25.2
  BOTTOM w0.114: J58.1 145.06,49.56 139.05,49.56 138.63,49.15 138.63,41.27 140.28,39.62 140.28,38.42 139.75,37.89 135.28,37.89 J56.1 ; J58.1 146.18,51.97 R195.1 ; J58.1 147,48.45 147.23,48.22 147.23,47.1 149.71,44.62 v1(156.51,44.62)
SDA_RX_EN: length 2.7
  TOP w0.114: R197.2 166.17,37.52 v1(166.17,38.22)
  BOTTOM w0.114: R78.1 v1(166.17,38.22) 165.91,37.95 U28.5
SDA_SPI0_CS: length 26.1
  TOP w0.114: v1(151.94,35.97) 152.37,35.97 152.6,36.2 152.6,36.65 R209.2
  BOTTOM w0.114: TP70.1 151.94,37.69 v1(151.94,35.97) 152.23,36.26 152.23,36.47 153.18,37.42 156.16,37.42 158.9,34.68 166.04,34.68 166.67,35.32 166.67,38.61 166.56,38.72 166.56,39.7 166.85,39.99 U26.23
SDA_SPI0_RST_B: length 30.4
  TOP w0.114: v1(146.58,41.02) 147.28,41.73 149.61,41.73 150.35,40.99 150.35,40.2 150.72,39.82 162.1,39.82 163.01,38.91 163.48,38.91 163.76,39.19 164.77,39.19 165.03,39.45 165.03,39.45 165.28,39.71 165.63,39.71 167.21,38.13 v2(167.21,37.59) 167.54,37.26 TP69.1
  BOTTOM w0.114: R208.2 146.58,40.2 v1(146.58,41.02) ; U26.22 167.35,40.15 166.8,39.6 166.8,38.92 167.21,38.51 v2(167.21,37.59)
SDA_SPI0_SCK: length 4.3
  BOTTOM w0.114: U29.3 162.43,41.11 162.68,40.86 TP77.1 164.2,40.86 165.28,41.93 U26.26
SDA_SPI0_SIN: length 6.6
  TOP w0.114: v2(164.26,42.19) 163.2,41.13 v3(163.2,39.35)
  BOTTOM w0.114: v3(163.2,39.35) 162.41,38.56 U19.3 ; U26.28 165,42.93 v2(164.26,42.19)
SDA_SPI0_SOUT: length 4.7
  BOTTOM w0.114: U20.3 163.77,43.6 163.79,43.58 TP75.1 163.79,41.77 163.91,41.66 164.45,41.66 165.23,42.43 U26.27
SDA_SWD_EN: length 2.5
  TOP w0.203: U27.6 149.33,38.96 148.89,39.4 148.26,39.4 R204.1
  vias: v3(147.9,40)
SDA_SWD_EN_B: length 43
  TOP w0.114: R189.2 142.7,38.3 142.32,37.92 v1(142.32,36.83)
  BOTTOM w0.114: v1(142.32,36.83) 144.22,34.92 151.89,34.92 152.86,35.89 152.86,36.2 152.99,36.33 152.99,36.33 153.6,36.94 155.96,36.94 158.7,34.2 166.24,34.2 166.77,34.73 169.38,34.73 169.57,34.54 171.22,34.54 172.41,35.73 172.41,40.26 171.24,41.43 U26.16
SDA_SWD_EN_B_R: length 5.4
  TOP w0.305: v3(144.86,38.3) 146.87,38.3 146.88,38.29 U27.1
  BOTTOM w0.508: v3(144.86,38.3) 145.49,38.3 145.52,38.33 147.02,38.33 147.32,38.63 R187.2
SDA_SWD_EN_R: length 18.6
  TOP w0.114: R204.2 146.3,40.71 146.1,40.91 146.1,41.58 146.66,42.14 v1(148.94,42.14)
  BOTTOM w0.114: v1(148.94,42.14) 149.47,42.67 156.79,42.67 157.05,42.42 157.05,41.91 157.9,41.06 R205.1 R206.2 160.01,41.06 160.18,41.24 160.56,41.61 U29.5
SDA_SWD_OE: length 3.5
  TOP w0.114: R84.1 151.43,37.01 R209.1 150.53,36.73 150.26,36.99 U27.4
SDA_SWD_OE_B: length 32.8
  BOTTOM w0.114: U26.20 168.35,40.32 167.95,39.92 167.95,37.58 166.92,36.54 166.92,35.22 166.14,34.44 158.8,34.44 156.06,37.18 153.5,37.18 152.75,36.43 152.75,36.43 152.61,36.3 152.61,35.99 152.01,35.39 144.85,35.39 v3(143.33,36.91)
SDA_SWD_OE_B_R: length 4.3
  TOP w0.114: R192.1 146.89,36.91 146.98,36.99 U27.3 147.49,36.58 147.52,36.55 v1(147.52,36.14)
  BOTTOM w0.114: v1(147.52,36.14) 147.45,36.21 R190.1
SDA_SWD_OE_R: length 25.9
  TOP w0.114: v1(148.08,41.32) 148.08,41.2 148.78,40.5 149.71,40.5 150.62,39.58 152.42,39.58 152.96,39.05 R84.2 ; R202.2 R201.1 162.57,44.38 v1(162.12,44.83)
  BOTTOM w0.114: v1(148.08,41.32) 148.08,41.96 149.05,42.93 157.17,42.93 157.43,42.67 159.83,42.67 160.14,42.98 160.53,42.98 160.74,43.19 160.74,43.8 161.48,44.54 161.83,44.54 v1(162.12,44.83) 162.26,44.69 U20.5
SDA_USB_CONN_DN: length 6
  TOP w0.108: J57.2 181.16,40.8 180.96,41 180.13,41 v2(179.85,40.72) 179.57,41 179.11,41 178.99,40.88 U17.1
  BOTTOM w0.108: R193.1 178.24,40.95 178.35,41.06 179.51,41.06 v2(179.85,40.72)
SDA_USB_CONN_DP: length 5.9
  TOP w0.108: J57.3 181.16,41.45 180.96,41.25 180.13,41.25 v2(179.85,41.53) 179.57,41.25 179.11,41.25 178.99,41.38 U17.2
  BOTTOM w0.108: R194.1 178.24,41.41 178.35,41.31 179.62,41.31 v2(179.85,41.53)
SDA_USB_DN: length 19.8
  BOTTOM w0.108: U26.4 167.85,46.12 167.73,46.25 167.73,48.26 168.1,48.62 175.77,48.62 176.36,48.04 176.36,41.31 176.61,41.06 177.12,41.06 177.23,40.95 R193.2
SDA_USB_DP: length 20.2
  BOTTOM w0.108: R194.2 177.23,41.41 177.12,41.31 176.71,41.31 176.61,41.41 176.61,48.14 175.87,48.87 167.99,48.87 167.48,48.36 167.48,46.25 167.35,46.12 U26.3
SDA_USB_P5V_SENSE: length 5.4
  TOP w0.114: TP76.1 166.16,45.19 R200.2 165.04,44.68 v2(164.83,44.47)
  BOTTOM w0.114: U26.30 165.37,43.93 v2(164.83,44.47) 165.14,44.78 165.14,45.7 R203.1
SDA_USBSHIELD:
  vias: v2(182.15,46.84) v2(182.96,33.27) v2(183.31,46.85) v2(184.3,46.86) v2(184.33,35.55) v2(184.33,34.28) v2(184.34,33.12)
SDA_VOUT33: length 12.3
  TOP w0.457: J61.2 173.61,44.7 173.18,45.13 173.18,47.12 171.53,48.77 C89.1 168.46,48.73 v2(168.46,46.84)
  BOTTOM w0.254: v2(168.46,46.84) 168.46,46.45 168.35,46.34 U26.5
SDA_XTAL: length 5.4
  BOTTOM w0.114: C87.1 167.57,36.53 168.41,37.37 X1.1 168.41,39.08 169.35,40.02 U26.18
SDB: length 3.7
  TOP w0.508: U5.1 150.6,17.88 151.11,17.37 v2(151.11,16.92)
  BOTTOM w0.508: v2(151.11,16.92) R21.2
SH_3V3_VDDIO_E: length 8.8
  TOP w0.254: U22.E5 v1(120.48,33.03)
  TOP w0.508: v2(119.89,26.67) 119.89,27.99 120.29,28.4 v2(120.29,29.27)
  BOTTOM w0.381: v1(120.48,33.03) 120.48,32.76 120.85,32.38 C49.1
  BOTTOM w0.508: v2(120.29,29.27) 120.38,29.27 120.85,29.74 C78.1 C49.1 ; v2(119.89,26.67) 119.94,26.67 120.45,26.16 SH3.1
SPARE_GPIO1: length 9.6
  TOP w0.114: U22.F4 121.12,33.04 121.12,32.52 120.96,32.36 119.95,32.36 119.84,32.25 119.84,28.56 119.28,28.01 119.28,26.39 TP58.1
SPARE_GPIO2: length 12.2
  TOP w0.114: v1(124.97,34.47) 124.18,33.68 121.78,33.68 U22.G3 ; TP59.1 v1(128.91,39.55)
  BOTTOM w0.114: v1(124.97,34.47) 124.97,35.61 126.69,37.34 126.69,38.35 127.89,39.55 v1(128.91,39.55)
SPARE_GPIO3: length 8.3
  TOP w0.114: TP60.1 125.75,38.07 125.29,38.07 123.48,36.26 121.93,36.26 121.78,36.11 121.78,34.46 121.64,34.31 121.12,34.31 U22.G4
SPARE_GPIO4: length 10.1
  TOP w0.114: v1(123.49,39.88) 123.79,40.17 123.79,40.5 TP61.1 ; U22.H4 v1(120.48,34.98)
  BOTTOM w0.114: v1(120.48,34.98) 120.27,35.18 120.27,39.05 121.11,39.88 v1(123.49,39.88)
SW1_RST_B: length 9.4
  TOP w0.114: J56.2 136.63,41.82 136.4,42.05 SW12.4 v1(133.43,42.61) SW12.3
  BOTTOM w0.114: v1(133.43,42.61) 133.43,43.12 C85.1
SWD_CLK_TGTMCU_BUF: length 33.2
  TOP w0.114: J60.2 141.09,44.72 146.84,44.72 147.87,45.75 147.87,48.1 149.17,49.4 153.24,49.4 153.75,48.89 155.86,48.89 156.95,47.81 159.66,47.81 161.23,46.24 161.23,44.28 160.73,43.78 v1(160.73,40.63)
  BOTTOM w0.114: U29.4 161.23,40.72 161.14,40.63 v1(160.73,40.63)
SWD_DIO_TGTMCU_BUF: length 47
  TOP w0.114: J59.2 144,44.96 146.74,44.96 147.62,45.85 147.62,48.2 149.07,49.64 153.34,49.64 153.83,49.15 155.94,49.15 156.96,48.13 159.75,48.13 161.47,46.42 161.47,44.56 161.53,44.5 v2(161.53,43.96) 162.06,43.96 163.39,42.63 164.44,42.63 164.7,42.38 164.7,41.94 166.78,39.86 166.78,39.06 168.11,37.73 168.11,35.83 167.22,34.95 165.04,34.95 164.4,35.59 v2(162.87,35.59)
  BOTTOM w0.114: U19.6 162.41,36.41 162.41,36.41 162.41,36.05 v2(162.87,35.59) ; U20.4 162.57,44.19 162.34,43.96 v2(161.53,43.96)
TC_EXTAL_TP: length 2.1
  BOTTOM w0.114: v3(172.44,44.73) 171.99,44.73 171.7,44.43 U26.10
TC_SDA_USB_ID_TP: length 5.4
  TOP w0.114: 179.82,42.71 180.43,42.1 J57.4 ; 179.82,42.71 179,41.89 179,41.88 U17.3 ; 179.82,42.71 179.82,43.87 TP65.1
TC_XTAL_TP: length 2.3
  BOTTOM w0.114: U26.9 171.13,44.93 171.93,45.73 172.03,45.73 v3(172.34,46.04)
TDI: length 4
  TOP w0.114: J35.8 119.47,45.69 119.93,46.15 R38.2 120.77,46.41 R47.1
TDO: length 3.2
  TOP w0.114: J35.6 118.92,47.44 119.52,47.44 120.77,48.69 R39.1
TP_2102_A: length 2.3
  TOP w0.114: U25.3 156.23,45.87 156.87,46.51 156.87,46.79 TP63.1
TP_2102_B: length 2.2
  TOP w0.114: U25.6 153.85,46.27 153.75,46.38 TP64.1
UART1_RX_TGTMCU: length 52.8
  TOP w0.114: U22.A5 120.48,30.42 123.42,30.42 v1(124,29.85) ; R196.2 164.5,36.72 163.44,36.72 161.43,38.73 155.87,38.73 152.86,35.72 v1(152.86,35.31)
  BOTTOM w0.114: v1(124,29.85) 125.16,29.85 126.14,28.87 135.63,28.87 135.97,29.21 135.97,30.61 136.35,30.99 138,30.99 138.51,31.5 138.51,32.64 139.9,34.04 151.59,34.04 v1(152.86,35.31)
UART1_RX_TGTMCU_BUF: length 1.9
  TOP w0.114: v1(165.45,39.29) 165.45,38.69 R196.1
  BOTTOM w0.114: U28.4 165.45,38.68 v1(165.45,39.29)
UART1_RX_TGTMCU_R: length 3.7
  TOP w0.114: v3(164.59,39.63) 164.59,40.18 v1(165.18,40.77)
  BOTTOM w0.114: U26.25 165.7,40.88 165.59,40.77 v1(165.18,40.77) ; U28.3 164.46,38.94 164.59,39.06 v3(164.59,39.63)
UART1_TX_TGTMCU: length 49.2
  TOP w0.114: U22.B5 120.48,31.07 123.74,31.07 v1(124.15,30.66)
  BOTTOM w0.114: v1(124.15,30.66) 124.88,31.39 135.48,31.39 135.71,31.62 135.71,34.67 136.73,35.69 140.83,35.69 141.9,36.76 141.9,37 144.08,39.18 152.28,39.18 153.8,37.67 156.26,37.67 158.74,35.18 159.91,35.18 159.92,35.18 R82.2
UART1_TX_TGTMCU_BUF: length 1.1
  BOTTOM w0.114: R82.1 U19.7
UART1_TX_TGTMCU_R: length 6.7
  BOTTOM w0.114: U19.2 TP71.1 162.31,40.26 166.04,40.26 166.35,40.57 U26.24
USB0_DM: length 4.2
  TOP w0.108: U22.H1 123.66,34.65 123.93,34.91 123.93,35.94 124.63,36.65 125.01,36.65 R9.2
USB0_DP: length 5
  TOP w0.108: U22.H2 122.43,34.33 123.69,34.33 124.17,34.81 124.17,35.84 124.73,36.4 125.07,36.4 R182.2
USB0_RDN: length 37.9
  TOP w0.108: v2(127.5,36.96) 127.23,36.68 126.77,36.68 R9.1
  BOTTOM w0.108: v2(127.5,36.96) 127.6,36.96 127.85,36.71 140.21,36.71 147.38,43.88 157.43,43.88 157.75,43.56 159.35,43.56 159.46,43.67 159.46,44.2 159.18,44.48 R25.1
USB0_RDP: length 38.3
  TOP w0.108: v2(127.5,36.15) 127.21,36.43 126.78,36.43 R182.1
  BOTTOM w0.108: v2(127.5,36.15) 127.82,36.46 140.31,36.46 147.48,43.63 157.32,43.63 157.64,43.31 159.46,43.31 159.71,43.57 159.71,44.2 159.99,44.48 R27.1
USB_5V_DC: length 1.2
  TOP w0.254: U22.J2 v1(122.43,35.63)
  BOTTOM w0.508: v1(122.43,35.63) 122.11,35.63 C47.1
  vias: v2(150,48.49) v2(150.9,48.51) v2(151.9,48.49) v2(152.81,48.51)
USB_5V_PA:
  vias: v2(179.72,48.75) v2(180.62,48.76) v2(181.1,49.92) v2(181.62,48.75) v2(182.02,49.9)
USB_CC1_DC: length 5.2
  TOP w0.114: J7.A5 160.49,51.9 160.6,51.79 v4(160.6,51.43)
  BOTTOM w0.114: v4(160.6,51.43) 160.84,51.2 160.99,51.2 161.24,50.95 161.24,49.15 161.78,48.61 v3(162.5,48.61)
USB_CC1_PA: length 9.1
  TOP w0.114: v1(176.1,51.51) 176.49,51.9 J6.A5
  BOTTOM w0.114: v1(176.1,51.51) 177.45,50.16 180.54,50.16 181.96,51.59 v3(182.96,51.59)
USB_CC2_DC: length 9.1
  TOP w0.114: J7.B5 158.74,53.19 158.68,53.13 v4(158.68,53.09)
  BOTTOM w0.114: v3(162.5,50.02) 162,50.52 162,53.47 161.03,54.44 159.17,54.44 158.68,53.96 v4(158.68,53.09)
USB_CC2_PA: length 12.1
  TOP w0.114: J6.B5 174.74,53.27 174.92,53.09 175.39,53.09 175.5,52.97 175.5,51.85 v1(175.21,51.56)
  BOTTOM w0.114: v3(182.88,53.01) 182.24,53.01 180.29,51.05 179.52,51.05 179.33,50.87 177.55,50.87 176.5,51.92 175.57,51.92 v1(175.21,51.56)
USB_DN: length 8.1
  TOP w0.108: J7.A7 158.99,52.26 159.37,51.88 159.37,51.61 v1(158.98,51.22) ; v4(159.87,53.13) 159.74,53.26 J7.B7
  BOTTOM w0.108: U2.A2 159.33,50.54 159.33,50.87 v1(158.98,51.22) 159.37,51.61 159.37,51.86 160.54,53.03 160.54,53.69 160.28,53.95 159.76,53.95 159.65,53.85 159.65,53.4 159.87,53.18 v4(159.87,53.13)
USB_DP: length 8.9
  TOP w0.108: J7.A6 159.99,52.26 159.62,51.88 159.62,51.61 v1(160,51.22) ; J7.B6 159.24,53.19 v4(159.24,53.12)
  BOTTOM w0.108: v4(159.24,53.12) 159.24,53.19 159.4,53.35 159.4,53.95 159.66,54.2 160.38,54.2 160.79,53.8 160.79,52.93 159.62,51.76 159.62,51.61 v1(160,51.22) 159.64,50.86 159.64,50.53 U2.A1
V_TGTMCU: length 17.3
  TOP w0.203: U25.8 153.84,45.47 v2(153.48,45.12)
  BOTTOM w0.305: v3(161.25,43.13) 161.25,42.6 161.23,42.58 U29.6 ; U28.6 C156.1 ; U19.8 161.33,37.34 160.63,37.34 v3(160.49,37.2) ; SH7.1 v2(135.84,41.27)
  BOTTOM w0.381: C159.1 163.01,46.19 U20.6
  BOTTOM w0.508: R191.1 174.7,35 174.21,34.51 172.18,34.51 v2(171.99,34.31) ; C156.1 164.52,36.4 164.13,36.01 v2(164.13,35.12) ; R185.1 136.7,43.03 v2(137.36,43.69) ; C159.1 162.78,46.41 162.4,46.41 161.87,46.94 v2(161.87,47.12) ; v2(153.48,45.12) 153.71,45.34 C81.1
  vias: v2(128.14,38.35)
VMAIN:
  vias: v2(132.87,10.66) v2(133.55,9.91) v2(134.14,10.66) v2(134.82,9.91) v2(168.35,18.29) v2(168.45,16.84) v2(169.47,16.84) v2(169.49,18.29) v2(170.03,26.38) v2(170.04,25.22) v2(171.3,26.38) v2(171.31,25.22)
VREF_OUT: length 6.2
  TOP w0.254: v1(122.12,37.34) 121.46,36.67 U22.L3
  TOP w0.381: v1(122.12,37.34) 123.77,37.34 v2(124.15,37.72)
  TOP w0.508: v2(124.15,37.72) 124.15,38.76 TP57.1
  BOTTOM w0.508: v1(122.12,37.34) 121.91,37.55 121.91,38.01 C48.1
VUP: length 2.2
  TOP w0.508: v2(95.14,41.45) 95.45,41.14 95.45,39.4
  vias: v2(94.13,41.45) v2(94.64,40.71)
XTAL32: length 2.7
  TOP w0.114: Y1.2 121.8,38.5 120.81,37.51 U22.L4
YELLOW_LED: length 24.3
  TOP w0.114: v1(163.18,12.28) 159.23,12.28 158.22,13.3 R16.3 157.74,21.54 157.59,21.69 157.59,27.18 J43.23
  BOTTOM w0.114: SJ7.1 v1(163.18,12.28)
N27599440: length 6
  TOP w0.505: J29.1 J30.1
N27599525: length 6
  TOP w0.505: J29.4 J30.4
N27867846: length 8.6
  TOP w0.114: TP52.1 81.07,19.1 84.45,22.47 84.45,23.03 85.48,24.06 P1.11
N27989341: length 77
  TOP w0.114: Q1.3 128.55,42.49 129.46,41.58 129.46,39.4 128.83,38.77 128.83,34.88 128.22,34.26 128.22,26.84 128.1,26.73 v1(126.82,26.73) ; v1(172.34,25.3) 173.94,25.3 174.47,25.83 175.75,25.83 176.36,25.22 D1.C
  BOTTOM w0.114: v1(126.82,26.73) 127.77,25.78 137.24,25.78 139.4,27.95 171.39,27.95 171.78,27.56 171.78,25.86 v1(172.34,25.3)
N27993186: length 7.4
  TOP w0.114: TP20.1 111.27,40.33 109.74,38.8 109.74,35.99 109.24,35.49 P1.41
N27993212: length 4.9
  TOP w0.114: P1.42 109.19,36.76 109.5,37.06 109.5,39.59 TP32.1
N28179141: length 2.8
  TOP w0.114: J28.8 R71.1
N28179177: length 28
  TOP w0.114: P1.24 100.53,15.47 101.8,14.2 104.88,14.2 104.89,14.19 v2(105.33,14.19) ; J28.4 v1(122.17,12.06) R64.1
  BOTTOM w0.114: v1(122.17,12.06) 107.46,12.06 v2(105.33,14.19)
N28179212: length 2.6
  TOP w0.508: J28.9 v2(117.17,17.96)
  BOTTOM w0.508: v2(117.17,17.96) SJ11.2
N28179372: length 2.4
  TOP w0.114: D11.A v1(178.79,14.71)
  BOTTOM w0.114: v1(178.79,14.71) 178.26,14.17 R62.2
N28179376: length 2.3
  TOP w0.114: D15.A v1(178.79,16)
  BOTTOM w0.114: R69.2 177.96,16.04 178,16 v1(178.79,16)
N28179481: length 84
  TOP w0.114: D11.C 176.39,12.25 173.37,9.23 155.43,9.23 153.66,7.45 153.66,4.02 152.06,2.42 135.67,2.42 130.25,7.84 120.14,7.84 118.56,6.26 114.06,6.26 111.5,3.71 109.72,3.71 108.88,4.55 106.86,4.55 v1(106.5,4.19)
  BOTTOM w0.114: v1(106.5,4.19) 106.5,3.26 Q6.3
N28179485: length 79.6
  TOP w0.114: D15.C 176.36,16 175.79,15.42 175.79,11.99 173.27,9.47 155.3,9.47 153.41,7.58 153.41,4.12 151.96,2.66 135.77,2.66 130.35,8.08 120.04,8.08 118.46,6.5 113.54,6.5 v1(111.21,4.18)
  BOTTOM w0.114: Q7.3 v1(111.21,4.18)
N28319858: length 6.4
  TOP w0.508: U7.1 168.69,20.49 170.28,18.9 R1.2 R4.1 R14.1
N28319891: length 2.9
  TOP w0.114: R3.2 170.51,16.11 170.51,16.79 R4.2
N28319921: length 2.3
  TOP w0.114: R14.2 172.67,16.69 172.55,16.57 R3.3
N28331755: length 2.1
  TOP w0.114: D16.A v1(178.79,17.3)
  BOTTOM w0.114: R164.2 178.13,17.4 178.23,17.3 v1(178.79,17.3)
N28331792: length 19.1
  TOP w0.114: D16.C 176.41,17.3 176.99,16.72 176.99,12.51 173.47,8.99 167.42,8.99 v1(167.13,8.7)
  BOTTOM w0.114: Q4.3 166.25,7.77 166.84,8.36 166.84,8.4 v1(167.13,8.7)
N28331794: length 2.2
  TOP w0.114: D17.A v1(178.79,18.62)
  BOTTOM w0.114: R165.2 178.25,18.75 178.38,18.62 v1(178.79,18.62)
N28331876: length 1.5
  BOTTOM w0.114: Q4.1 164.01,10.41 163.98,10.43 SJ7.2
N28331878: length 2.1
  TOP w0.114: D18.A v1(178.79,20.17)
  BOTTOM w0.114: R172.2 v1(178.79,20.17)
N28331886: length 28.6
  TOP w0.114: v1(162.23,7.77) 166.79,7.77 167.6,8.59 173.4,8.59 179.3,14.48 179.3,18.81 178.92,19.2 176.52,19.2 176.39,19.06 D17.C
  BOTTOM w0.114: Q5.3 v1(162.23,7.77)
N28332010: length 33.2
  TOP w0.114: v1(158.67,7.77) 159.16,7.29 166.65,7.29 167.7,8.34 173.5,8.34 179.55,14.38 179.55,18.93 178.89,19.58 177,19.58 176.41,20.17 D18.C
  BOTTOM w0.114: Q2.3 v1(158.67,7.77)
N28332022: length 1.4
  BOTTOM w0.114: SJ8.2 Q5.1
N28332036: length 2.1
  TOP w0.114: D19.A v1(178.79,21.46)
  BOTTOM w0.114: R173.2 v1(178.79,21.46)
N28332155: length 7.4
  TOP w0.114: R127.1 131.11,35.95 130.89,35.72 130.89,31.02 J43.5
N28332189: length 7.6
  TOP w0.114: R137.1 129.59,35.03 128.5,33.93 128.5,30.87 J43.3
N28332225: length 5.7
  TOP w0.114: J43.40 176.48,31.15 v1(176.48,28.83)
  BOTTOM w0.114: R142.2 176.2,27.66 176.48,27.94 v1(176.48,28.83)
N28332293: length 40.3
  TOP w0.114: D19.C 176.41,21.46 176.99,22.04 178.97,22.04 179.79,21.23 179.79,14.28 173.6,8.1 167.97,8.1 166.8,6.93 155.57,6.93 v1(154.74,7.77)
  BOTTOM w0.114: Q3.3 v1(154.74,7.77)
N28332350: length 62.9
  TOP w0.114: v1(131.67,27.58) 127.38,23.29 115.7,23.29 115.52,23.11 115.52,23.1 114.85,22.44 R141.2
  BOTTOM w0.114: J43.38 171.64,31.27 138.86,31.27 138.28,30.68 138.28,29.37 136.5,27.58 v1(131.67,27.58)
N28421669: length 1.4
  BOTTOM w0.114: SJ9.2 Q2.1
N28421722: length 1.4
  BOTTOM w0.114: SJ10.2 Q3.1
N28430174: length 39.1
  TOP w0.114: v1(91.26,8.38) 91.26,10.54 93.37,12.65 95.68,12.65 96.01,12.32 100.79,12.32 101.8,11.3 104.98,11.3 106.33,12.66 106.33,14.28 106.82,14.77 111.77,14.77 112.62,15.62 R8.3
  BOTTOM w0.114: v1(91.26,8.38) 90.32,7.44 90.32,3.49 89.88,3.05 J10.1
N28430681: length 2.2
  TOP w0.114: v2(103.25,2.21) SJ3.2
  BOTTOM w0.114: v2(103.25,2.21) Q6.1
N28430684: length 1.8
  TOP w0.114: v2(108.29,2.23) SJ4.2
  BOTTOM w0.114: Q7.1 v2(108.29,2.23)
N28495927: length 71.3
  TOP w0.114: D3.C 175.88,24.41 174.94,24.41 v1(174.5,23.98)
  BOTTOM w0.114: Q9.3 114.99,21.49 117.05,19.42 121.24,19.42 121.5,19.16 124.26,19.16 v1(124.56,19.45) 124.98,19.45 127.91,16.53 136.43,16.53 136.86,16.1 154.1,16.1 157.33,19.34 170.54,19.34 170.89,19.69 173.05,19.69 174.83,21.46 174.83,23.65 v1(174.5,23.98)
N28496386: length 51.9
  TOP w0.114: TP62.1 126.28,50.03 126.3,50.01 R184.2 C154.1 v1(128.73,50.01) 130.01,48.73 SW1.3 SW1.4
  BOTTOM w0.114: U23.1 109.59,28.69 108.63,29.64 108.63,38.48 115.3,45.15 115.3,50.22 115.97,50.9 127.85,50.9 v1(128.73,50.01)
N28503659: length 32
  TOP w0.114: R16.1 158.81,22.79 158.98,22.96 158.98,24.66 163.06,28.75 v1(172.25,28.75)
  BOTTOM w0.114: J27.4 182.69,27.05 178.87,27.05 178.35,26.52 172.9,26.52 172.76,26.67 172.76,28.24 v1(172.25,28.75)
N28503664: length 43.8
  TOP w0.114: R15.1 156.64,22.7 157.1,23.17 157.1,24.61 156.44,25.27 154.94,25.27 153.59,26.62 153.59,30.38 154.35,31.14 155.07,31.14 156.21,32.28 156.21,33.2 v1(156.67,33.66)
  BOTTOM w0.114: J27.2 183.1,32.05 178.72,32.05 177.47,33.3 157.02,33.3 v1(156.67,33.66)
N28509733: length 3.6
  TOP w0.114: J43.24 156.16,33.57 v1(156.16,34.29)
  BOTTOM w0.114: v1(156.16,34.29) 155.9,34.55 R122.2
N28509890: length 5.9
  TOP w0.114: v1(152.86,34.04) 153.36,33.54 153.36,30.76 J43.21
  BOTTOM w0.114: R144.1 153.37,34.55 v1(152.86,34.04)
N28538592: length 2.6
  TOP w0.114: SJ12.2 118.53,24.93 118.37,24.77 v1(117.95,24.77)
  BOTTOM w0.114: v1(117.95,24.77) 118.43,24.77 118.61,24.59 Q8.1
N28538615: length 2.7
  TOP w0.114: v1(116.41,25.65) 116.56,25.5 SJ13.2
  BOTTOM w0.114: v1(116.41,25.65) 116.41,24.82 Q9.1
N28539455: length 59.7
  TOP w0.114: v1(174.19,23.34) 175.72,23.34 176.36,22.69 D2.C
  BOTTOM w0.114: v1(174.19,23.34) 173.78,23.75 158.06,23.75 156.79,25.02 145.87,25.02 142.7,21.84 126.44,21.84 125.68,22.61 120.15,22.61 119.55,22.01 Q8.3
N28651788: length 2.8
  BOTTOM w0.114: J43.37 173.4,29.15 173.4,28.09 173.43,28.06 R152.1
N28673617: length 1.4
  BOTTOM w0.108: R12.1 159.61,49.06 159.61,49.43 159.68,49.51 U2.C1
N28673619: length 2.3
  BOTTOM w0.108: R12.2 159.7,47.1 159.7,46.11 159.81,46 v3(160.4,46)
N28673663: length 1.4
  BOTTOM w0.108: U2.C2 159.28,49.51 159.36,49.43 159.36,49.04 R19.1
N28673665: length 2.5
  BOTTOM w0.108: v3(158.75,46) 159.31,46 159.45,46.14 159.45,47.04 158.97,47.52 R19.2

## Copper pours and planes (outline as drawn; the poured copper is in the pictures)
1V8_VDD on TOP: 159.66,24.77 164.03,24.77 165.3,23.5 173.73,23.5 174.85,22.38 174.85,13.84 174.6,13.59 172.67,13.59 172.67,14.35 173.56,15.24 173.56,19.05 172.92,19.69 170.31,19.69 167.92,22.07 165.25,22.07 164.11,20.93 159.76,20.93 159.51,21.18 159.51,24.61
1V8_VDD on BOTTOM: 165.43,23.5 172.92,23.5 173.05,23.37 173.05,20.57 172.16,19.69 169.62,19.69 169.49,19.81 169.49,21.46 168.73,22.23 165.43,22.23 165.3,22.35 165.3,23.37
3V3_5V0 on TOP: 145.21,26.95 145.72,26.44 145.72,24.77 144.83,23.88 144.83,19.91 145.13,19.61 145.13,16.41 144.98,16.26 144.19,16.26 143.94,16.51 143.94,20.45 143.51,20.88 139.83,20.88 139.6,21.11 138.45,21.11 138.15,21.41 138.15,25.96 139.14,26.95
3V3_5V0 on L3_INT_1: 126.31,31.5 127.46,30.35 130.12,30.35 130.5,30.73 143.84,30.73 145.49,29.08 145.49,24.51 145.11,24.13 142.19,24.13 140.03,26.29 126.82,26.29 124.28,28.83 124.28,32.77 123.77,33.27 123.77,49.02 121.61,51.18 116.28,51.18 114.38,49.28 88.09,49.28 86.82,50.55 86.82,52.32 87.45,52.96 124.41,52.96 126.31,51.05
3V3_VDD on TOP: 159.26,16.74 164.26,16.74 165.61,15.39 168.63,15.39 169.7,14.33 170.43,14.33 170.56,14.2 170.56,12.95 170.1,12.5 168.93,12.5 168.54,12.89 168.54,13.73 168.12,14.15 165.61,14.15 164.29,12.83 159.59,12.83 159.13,13.28 159.13,16.61
3V3_VDD on BOTTOM: 165.05,15.88 169.87,15.88 170.51,15.24 170.51,12.45 170.13,12.07 168.1,12.07 167.84,12.32 167.84,13.08 168.1,13.34 168.1,14.48 167.72,14.86 165.05,14.86
3V3_VDD on L3_INT_1: 176.73,26.8 176.73,16.13 175.72,15.11 172.67,15.11 169.24,11.68 163.4,11.68 157.56,5.84 142.57,5.84 142.19,6.22 112.47,6.22 110.95,4.7 100.15,4.7 99.26,5.59 99.26,9.27 103.71,13.72 115.01,13.72 116.03,14.73 116.03,16.64 115.52,17.14 113.74,17.14 112.72,18.16 112.72,25.91 113.74,26.92 116.92,26.92 117.17,26.67 117.17,20.57 119.07,18.67 129.74,18.67 130.38,18.03 130.38,9.78 131.27,8.89 152.22,8.89 158.32,14.99 169.87,14.99 172.16,17.27 172.16,25.53 173.43,26.8
GND on TOP: 76.78,59.37 185.52,59.37 185.52,32.64 180.03,32.64 179.78,32.89 179.78,34.54 175.59,34.54 175.59,38.23 180.54,38.23 180.54,42.29 176.1,42.29 176.1,46.35 176.86,46.35 176.86,47.62 173.18,47.62 173.18,44.2 169.62,44.2 169.62,41.53 166.57,41.53 166.57,47.37 166.32,47.62 164.41,47.62 163.27,46.48 163.27,45.08 162.38,45.08 162.38,49.91 167.46,49.91 167.46,46.1 172.8,46.1 172.8,50.42 166.83,50.42 166.83,54.74 160.73,54.74 160.73,44.25 157.43,44.25 157.43,48.26 153.87,48.26 153.87,45.47 151.71,45.47 151.71,42.54 146.76,42.54 143.33,39.12 143.33,34.42 150.9,34.42 151.37,33.95 151.37,23.03 151.33,22.99 155.14,22.99 155.14,16.26 152.35,13.46 152.35,11.68 163.91,11.68 164.92,12.7 164.92,17.4 158.7,17.4 158.7,20.37 164.29,20.37 164.29,23.5 165.43,23.5 165.43,19.35 167.97,19.35 167.97,9.78 155.4,9.78 153.36,7.75 153.36,6.22 153.49,6.1 181.94,6.1 183.08,4.95 185.37,4.95 185.37,19.94 179.3,19.94 179.3,24.26 185.52,24.26 185.52,0.63 76.78,0.63 ; 25 cut-outs
GND on L2_GND_1: 185.52,59.37 185.52,0.63 76.78,0.63 76.78,21.26 55.01,21.26 55.01,38.79 76.78,38.79 76.78,59.37
GND on L3_INT_1: 185.52,59.37 185.52,0.63 76.78,0.63 76.78,59.37 ; 7 cut-outs
P3V3_SDA on TOP: 158.57,44.07 158.83,43.81 158.83,43.05 159.08,42.8 160.35,42.8 160.6,42.54 160.6,42.04 160.35,41.78 157.3,41.78 156.79,41.27 155.52,41.27 155.52,42.04 154.76,42.8 154.76,43.81 155.02,44.07
P3V3_SDA on L3_INT_1: 164.42,47.37 163.78,47.37 162.76,46.35 162.76,42.93 162.75,42.92 162.75,42.78 162.06,42.08 162.06,39.08 161.52,38.55 160.23,38.55 160.1,38.41 160.1,38 160.24,37.85 162.13,37.85 163.4,36.58 164.03,36.58 164.16,36.7 164.54,36.7 165.81,35.43 172.55,35.43 173,34.98 173,33.87 172.28,33.15 158.32,33.15 155.97,35.49 155.97,38.58 156.77,39.38 156.78,39.38 157.23,39.83 157.23,41.84 156.79,42.28 156.79,42.28 156.5,42.58 147.68,42.58 146.89,41.78 146.89,37.21 148.41,35.69 151.97,35.69 154.38,33.27 154.38,26.16 155.27,25.27 163.02,25.27 168.1,30.35 174.32,30.35 175.08,31.12 175.08,37.72 174.7,38.1 170.64,38.1 170,38.73 170,41.15 170.51,41.66 174.7,41.66 175.59,42.54 175.59,47.44 175.23,47.8 174.19,47.8 173.98,47.58 173.98,47.37 173.84,47.24 170.5,47.24 170,46.74 170,46.58 170.2,46.38 170.2,45.06 169.46,44.32 165.35,44.32 165.33,44.34 165.2,44.34 164.86,44.68 164.86,47.33 165.38,47.85 165.38,48.09 165.26,48.2 164.77,48.2 164.57,48 164.57,47.52
P5V_SDA on TOP: 180.49,37.69 176.53,37.69 176.15,37.31 176.15,34.72 176.3,34.57 178.81,34.57 179.4,35.15 179.4,35.92 179.68,36.2 180.52,36.2 180.57,36.25 180.57,37.62
P5V_SDA on L3_INT_1: 165.43,45.47 165.43,45.15 165.64,44.95 165.83,44.95 166.37,44.4 169.26,44.4 169.79,44.93 169.79,47.09 169.58,47.3 169.58,47.31 168.97,47.31 168.8,47.14 168.8,45.66 168.58,45.44 166.94,45.44 166.75,45.62 166.75,45.65 166.14,46.26 166.14,46.85 166.75,47.47 166.75,49.03 167.29,49.57 176.63,49.57 177.31,48.88 177.31,44.59 180.21,41.69 180.21,39.85 179.99,39.62 176.91,39.62 175.51,41.02 170.76,41.02 170.51,40.77 170.51,38.86 170.76,38.61 175.08,38.61 175.72,37.97 175.72,34.54 176.22,34.04 179.24,34.04 182.04,36.84 182.04,45.68 180.16,47.56 178.94,47.56 178.51,47.99 178.51,49.78 178.13,50.16 166.83,50.16 165.94,49.28 165.94,47.62 165.43,47.11 165.43,45.85
VBAT on TOP: 95.91,34.34 98.45,34.34 98.83,34.72 98.83,37.64 98.57,37.89 95.78,37.89 95.27,37.38 95.27,34.97
VBAT on BOTTOM: 95.91,34.34 98.45,34.34 98.91,34.8 98.91,35.91 98.7,36.11 98.7,37.64 98.45,37.89 95.78,37.89 95.27,37.38 95.27,34.97
VBAT on L3_INT_1: 85.91,50.53 85.91,52.4 85.49,52.82 84.28,52.82 83.27,51.81 83.27,44.13 84.46,42.94 95.21,42.94 96.11,42.04 96.11,35.02 96.69,34.44 101.57,34.44 102.44,35.31 102.44,47.35 101.43,48.35 88.09,48.35
VBATPWR on TOP: 100.73,40.43 101.11,40.43 101.37,40.18 101.37,38.65 101.49,38.53 102.13,38.53 102.26,38.65 102.26,41.6 101.9,41.96 100.73,41.96 100.6,41.83 100.6,40.56
VBATPWR on BOTTOM: 102.38,40.43 102.38,41.94 102.31,42.02 101.85,42.02 101.68,42.18 101.68,42.22 101.68,45.22 101.48,45.42 100.73,45.42 100.48,45.16 100.48,40.43 100.73,40.18 102.13,40.18
